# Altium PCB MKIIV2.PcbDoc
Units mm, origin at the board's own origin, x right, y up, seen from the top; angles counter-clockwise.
Board outline 51.16 x 28.42 mm, 2 copper layers (Top Layer, Bottom Layer); 24 components, 0 nets, 95 pads, 0 vias.
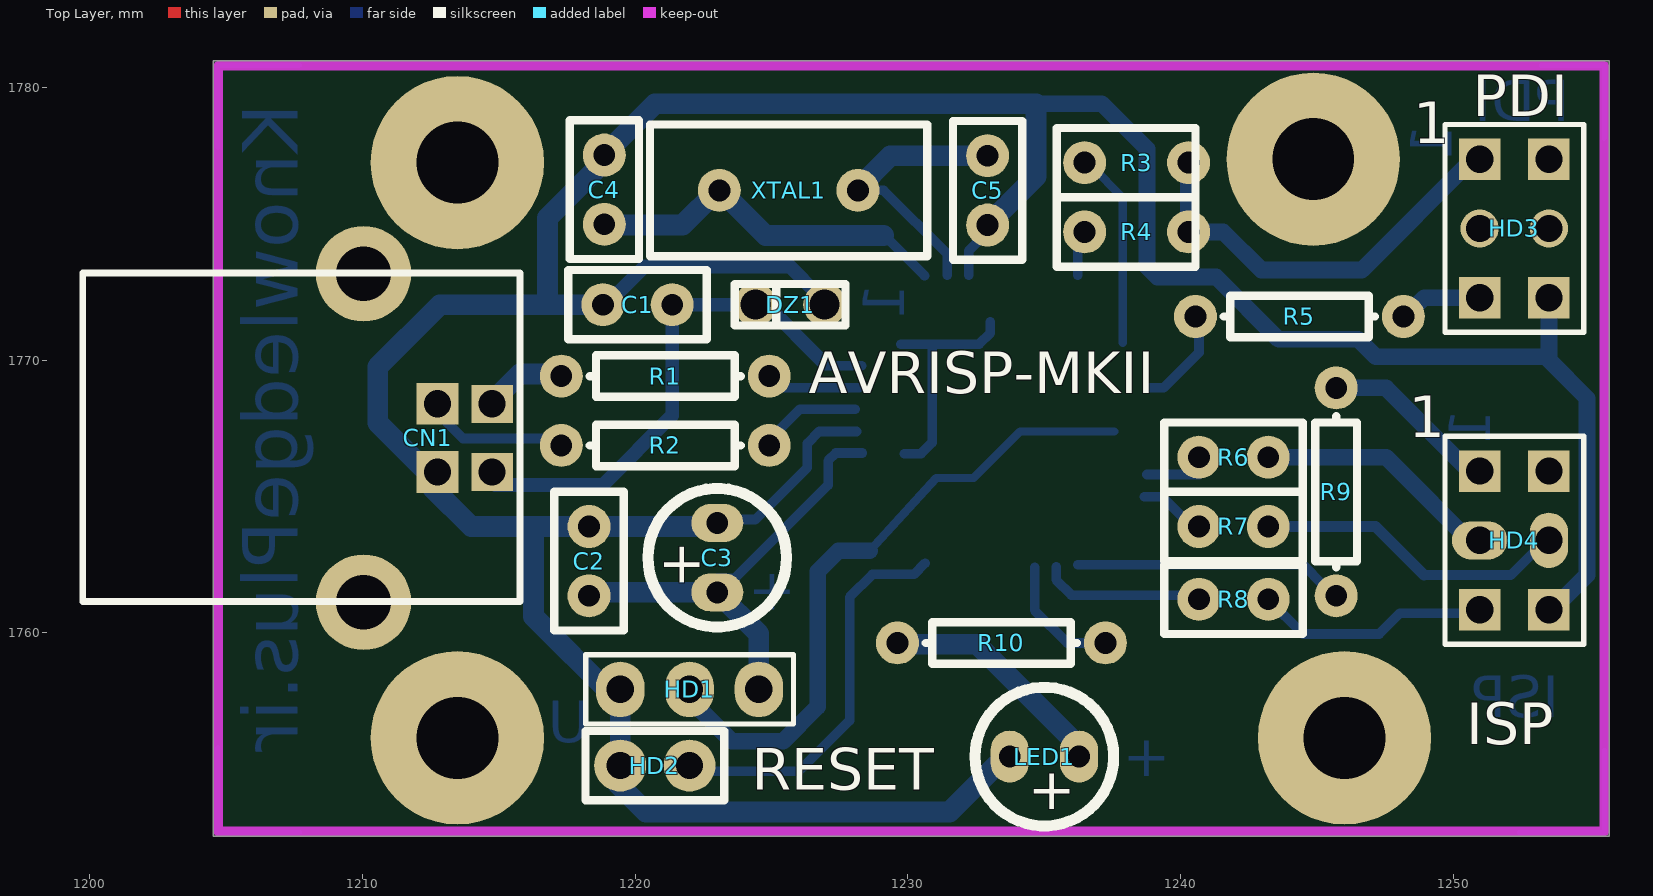
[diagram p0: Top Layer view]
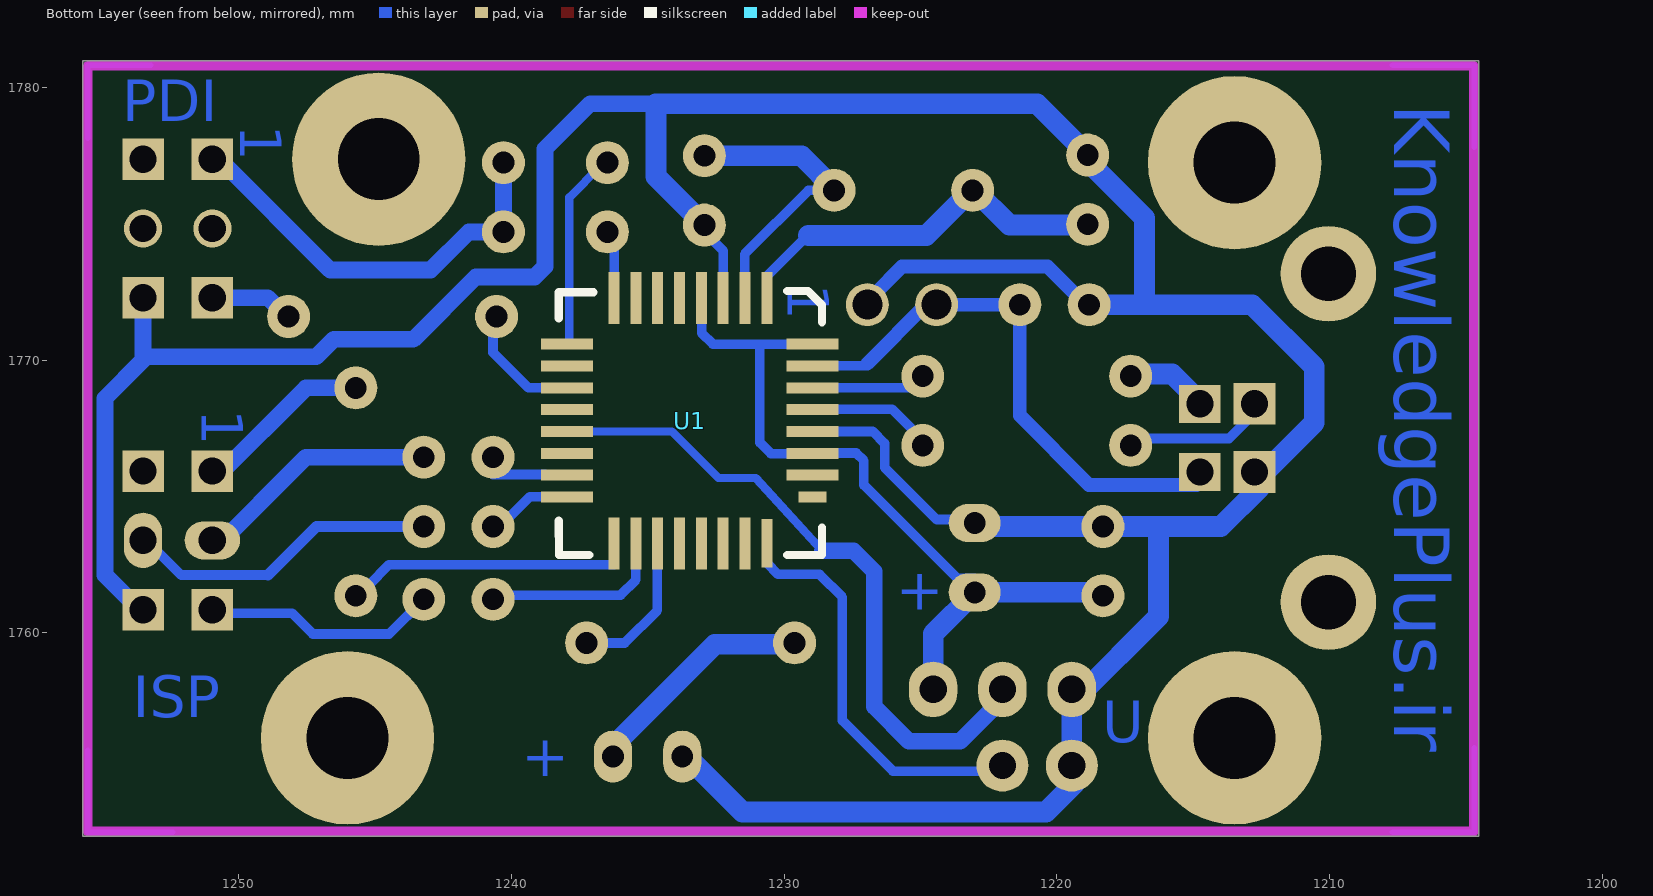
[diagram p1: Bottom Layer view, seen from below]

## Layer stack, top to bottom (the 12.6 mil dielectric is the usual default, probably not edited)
Top Layer: signal copper 0.0356
Dielectric: dielectric 0.32, FR-4, Dk 4.8
Bottom Layer: signal copper 0.0356

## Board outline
1204.544,1752.549 1255.7,1752.549 1255.7,1780.972 1204.544,1780.972

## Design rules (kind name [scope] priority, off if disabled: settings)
Clearance [All] p1: gap=0.254
PlaneClearance PlaneClearance_20 [HasPad('HD2-1')] p1: clearance=0.254
PlaneClearance PlaneClearance_19 [HasPad('HD2-2')] p2: clearance=0.254
PlaneClearance PlaneClearance_18 [HasPad('R10-1')] p3: clearance=0.254
PlaneClearance PlaneClearance_17 [HasPad('R10-2')] p4: clearance=0.254
PlaneClearance PlaneClearance_16 [HasPad('LED1-0')] p5: clearance=0.254
PlaneClearance PlaneClearance_15 [HasPad('CN1-0')] p6: clearance=0.254
PlaneClearance PlaneClearance_14 [HasPad('R1-1')] p7: clearance=0.254
PlaneClearance PlaneClearance_13 [HasPad('R1-2')] p8: clearance=0.254
PlaneClearance PlaneClearance_12 [HasPad('DZ1-0')] p9: clearance=0.254
PlaneClearance PlaneClearance_11 [HasPad('C3-0')] p10: clearance=0.254
PlaneClearance PlaneClearance_10 [HasPad('R2-2')] p11: clearance=0.254
PlaneClearance PlaneClearance_9 [HasPad('R2-1')] p12: clearance=0.254
PlaneClearance PlaneClearance_8 [HasPad('R5-2')] p13: clearance=0.254
PlaneClearance PlaneClearance_7 [HasPad('R5-1')] p14: clearance=0.254
PlaneClearance PlaneClearance_6 [HasPad('R9-1')] p15: clearance=0.254
PlaneClearance PlaneClearance_5 [HasPad('R9-2')] p16: clearance=0.254
PlaneClearance PlaneClearance_4 [HasPad('Free-1')] p17: clearance=0.254
PlaneClearance PlaneClearance_3 [HasPad('Free-2')] p18: clearance=0.254
PlaneClearance PlaneClearance_2 [HasPad('Free-3')] p19: clearance=0.254
PlaneClearance PlaneClearance_1 [HasPad('Free-4')] p20: clearance=0.254
PlaneClearance [All] p21: clearance=0.508
PolygonConnect [All] p1: connectstyle=Relief reliefconductorwidth=0.254 reliefentries=4 polygonreliefangle="90 Angle" airgapwidth=0.254
RoutingVias [All] p1: holewidth=0.711 width=1.27 viastyle="Through Hole" minholewidth=0.711 minwidth=1.27 maxholewidth=0.711 maxwidth=1.27
SolderMaskExpansion SolderMaskExpansion_24 [HasPad('HD1-1')] p1: expansion=0.102
SolderMaskExpansion SolderMaskExpansion_23 [HasPad('HD1-2')] p2: expansion=0.102
SolderMaskExpansion SolderMaskExpansion_22 [HasPad('HD1-3')] p3: expansion=0.102
SolderMaskExpansion SolderMaskExpansion_21 [HasPad('C1-0')] p4: expansion=0.102
SolderMaskExpansion SolderMaskExpansion_20 [HasPad('C2-0')] p5: expansion=0.102
SolderMaskExpansion SolderMaskExpansion_19 [HasPad('XTAL1-0')] p6: expansion=0.102
SolderMaskExpansion SolderMaskExpansion_18 [HasPad('C4-0')] p7: expansion=0.102
SolderMaskExpansion SolderMaskExpansion_17 [HasPad('C5-0')] p8: expansion=0.102
SolderMaskExpansion SolderMaskExpansion_16 [HasPad('R3-0')] p9: expansion=0.102
SolderMaskExpansion SolderMaskExpansion_15 [HasPad('R4-0')] p10: expansion=0.102
SolderMaskExpansion SolderMaskExpansion_14 [HasPad('R6-0')] p11: expansion=0.102
SolderMaskExpansion SolderMaskExpansion_13 [HasPad('R7-0')] p12: expansion=0.102
SolderMaskExpansion SolderMaskExpansion_12 [HasPad('R8-0')] p13: expansion=0.102
SolderMaskExpansion SolderMaskExpansion_11 [HasPad('HD3-VCC')] p14: expansion=0.102
SolderMaskExpansion SolderMaskExpansion_10 [HasPad('HD3-RST')] p15: expansion=0.102
SolderMaskExpansion SolderMaskExpansion_9 [HasPad('HD3-GND')] p16: expansion=0.102
SolderMaskExpansion SolderMaskExpansion_8 [HasPad('HD3-')] p17: expansion=0.102
SolderMaskExpansion SolderMaskExpansion_7 [HasPad('HD3-PDI')] p18: expansion=0.102
SolderMaskExpansion SolderMaskExpansion_6 [HasPad('HD4-MISO')] p19: expansion=0.102
SolderMaskExpansion SolderMaskExpansion_5 [HasPad('HD4-MOSI')] p20: expansion=0.102
SolderMaskExpansion SolderMaskExpansion_4 [HasPad('HD4-SCK')] p21: expansion=0.102
SolderMaskExpansion SolderMaskExpansion_3 [HasPad('HD4-GND')] p22: expansion=0.102
SolderMaskExpansion SolderMaskExpansion_2 [HasPad('HD4-RST')] p23: expansion=0.102
SolderMaskExpansion SolderMaskExpansion_1 [HasPad('HD4-VCC')] p24: expansion=0.102
SolderMaskExpansion [All] p25: expansion=0.051
Width [All] p1: maxlimit=0.254 minlimit=0.254 preferedwidth=0.254
27 further rules are at their usual default settings.

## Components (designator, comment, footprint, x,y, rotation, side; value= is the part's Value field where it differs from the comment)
C1 "100nF" RAD0.1#1 1218.819,1772.031 r0 top
C2 "100nF" RAD0.1#1 1218.311,1761.363 r90 top
C3 "1uF" RB.1/.2 1223.01,1761.49 r90 top
C4 "18pF" RAD0.1#1 1218.87,1777.517 r270 top
C5 "18pF" RAD0.1#1 1232.916,1774.952 r90 top
CN1 "USB B connector" USB_B 1210.056,1773.174 r270 top
DZ1 "1N4734" DIODE0.1 1224.407,1772.031 r270 top
HD1 "1x3 Pin header+jumper" VR5 1221.994,1757.934 r0 top
HD2 "1x2 Pin header+jumper" RAD0.1#2 1219.454,1755.14 r0 top
HD3 "2x3 Pin header" HDR2X3#1 1250.95,1777.365 r270 top
HD4 "2x3 Pin header" HDR2X3#2 1250.95,1765.935 r270 top
LED1 "LED" RB.1/.2 1236.269,1755.47 r180 top
R1 "22 ohm" AXIAL0.3 1224.915,1769.364 r180 top
R2 "22 ohm" AXIAL0.3 1224.915,1766.824 r180 top
R3 "220 ohm" RAD0.1#3 1236.726,1777.238 r0 top
R4 "220 ohm" RAD0.1#3 1236.726,1774.698 r0 top
R5 "33 ohm" AXIAL0.3 1240.536,1771.65 r0 top
R6 "33 ohm" RAD0.1#1 1240.663,1766.443 r0 top
R7 "33 ohm" RAD0.1#1 1240.663,1763.903 r0 top
R8 "33 ohm" RAD0.1#1 1240.663,1761.236 r0 top
R9 "33 ohm" AXIAL0.3 1245.743,1768.983 r270 top
R10 "470 ohm" AXIAL0.3 1237.234,1759.585 r180 top
U1 "AT90usb162" QFP32 1230.63,1772.285 r270 top
XTAL1 "8MHz" XTAL1 1228.166,1776.222 r180 top

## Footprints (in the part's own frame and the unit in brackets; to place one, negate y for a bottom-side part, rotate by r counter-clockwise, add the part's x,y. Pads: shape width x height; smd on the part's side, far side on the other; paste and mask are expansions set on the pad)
AXIAL0.3 [mil]
  round 62 hole 31.5: 1(0,-2) 2(300,-2)
  silkscreen extent 41,-32 259,28
DIODE0.1 [mil]
  round 62 hole 43.31: 0(0,100) 0(0,0)
  silkscreen extent -30,-30 30,130
HDR2X3#1 [mil]
  rect 60x60 hole 39.37: GND(200,100) PDI(0,0) RST(200,0) VCC(0,100)
  round 55 hole 39.37: ""(100,100) ""(100,0)
  silkscreen extent -50,-50 250,150
HDR2X3#2 [mil]
  rect 60x60 hole 39.37: GND(200,100) MISO(0,0) RST(200,0) VCC(0,100)
  oval 80x55 hole 39.37: MOSI(100,100)
  oval 55x80 hole 39.37: SCK(100,0)
  silkscreen extent -50,-50 250,150
QFP32 [mm]
  rect 1.905x0.406 smd far side: 1(0,0) 2(0,0.8) 3(0,1.6) 4(0,2.4) 5(0,3.2) 6(0,4) 7(0,4.8) 8(0,5.6) 17(9,5.6) 18(9,4.8) 19(9,4) 20(9,3.2) 21(9,2.4) 22(9,1.6) 23(9,0.8)
  rect 0.406x1.905 smd far side: 9(1.7,7.325) 10(2.5,7.325) 11(3.3,7.325) 12(4.1,7.325) 13(4.9,7.325) 14(5.7,7.325) 15(6.5,7.325) 16(7.3,7.325) 26(6.5,-1.675) 27(5.7,-1.675) 28(4.9,-1.675) 29(4.1,-1.675) 30(3.3,-1.675) 31(2.5,-1.675) 32(1.7,-1.675)
  rect 1.778x0.406 smd far side: 24(9,0)
  rect 0.406x1.016 smd far side: 25(7.3,-1.675)
RAD0.1#1 [mil]
  round 62 hole 31.5: 0(0,0) 0(100,0)
  silkscreen extent -50,-50 150,50
RAD0.1#2 [mil]
  round 75 hole 39.37: 1(0,0) 2(100,0)
  silkscreen extent -50,-50 150,50
RAD0.1#3 [mil]
  round 62 hole 31.5: 0(-10,0) 0(140,0)
  silkscreen extent -50,-50 150,50
RB.1/.2 [mm]
  oval 1.397x1.905 hole 0.8: 0(0,0) 0(2.54,0)
  silkscreen extent -1.27,-2.54 3.81,2.54
USB_B [mm]
  round 3.5 hole 2: 0(0.005,-0.01) 0(12.045,-0.01)
  rect 1.524x1.524 hole 1: 0(4.775,2.7) 0(7.275,2.7)
  rect 1.397x1.524 hole 1: 0(4.775,4.7) 0(7.275,4.7)
  silkscreen extent -0.03,-10.3 12.03,5.72
VR5 [mil]
  oval 70x80 hole 39.37: 1(-100,0) 2(0,0) 3(100,0)
  silkscreen extent -150,-50 150,50
XTAL1 [mil]
  round 62 hole 31.5: 0(0,0) 0(200,0)
  silkscreen extent -100,-95 300,95

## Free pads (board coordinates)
  round 6.35 hole 3: 1(1244.854,1777.365) 2(1245.997,1756.156) 3(1213.485,1756.156) 4(1213.485,1777.238)

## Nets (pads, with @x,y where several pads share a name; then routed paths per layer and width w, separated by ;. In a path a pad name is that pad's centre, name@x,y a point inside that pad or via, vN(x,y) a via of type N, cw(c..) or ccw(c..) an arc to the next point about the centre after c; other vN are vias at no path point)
pads on no net: C1.0 C2.0 C3.0 C4.0 C5.0 CN1.0 DZ1.0 HD1.1 HD1.2 HD1.3 HD2.1 HD2.2 HD3. HD3.GND HD3.PDI HD3.RST HD3.VCC HD4.GND HD4.MISO HD4.MOSI HD4.RST HD4.SCK HD4.VCC LED1.0 R1.1 R1.2 R2.1 R2.2 R3.0 R4.0 R5.1 R5.2 R6.0 R7.0 R8.0 R9.1 R9.2 R10.1 R10.2 U1.1 U1.2 U1.3 U1.4 U1.5 U1.6 U1.7 U1.8 U1.9 U1.10 U1.11 U1.12 U1.13 U1.14 U1.15 U1.16 U1.17 U1.18 U1.19 U1.20 U1.21 U1.22 U1.23 U1.24 U1.25 U1.26 U1.27 U1.28 U1.29 U1.30 U1.31 U1.32 XTAL1.0
copper on no net: | length 374.4
  Bottom Layer w0.203: 1204.7,1755.8 1204.7,1752.7 1207.7,1752.7 ; 1204.7,1777.8 1204.7,1780.8 1207.7,1780.8 ; 1252.4,1752.7 1255.522,1752.7 1255.522,1755.7 ; 1253.2,1780.8 1255.522,1780.8 1255.522,1778.127
  Bottom Layer w0.305: 1228.598,1763.014 1231.036,1765.681 1232.408,1765.681 1234.11,1767.383 1237.564,1767.383 ; 1236.726,1777.111 1237.869,1775.968 1237.869,1770.634
  Bottom Layer w0.356: 1212.723,1768.094 1213.688,1767.129 1216.863,1767.129 ; 1222.273,1754.937 1226.007,1754.937 1227.861,1756.791 1227.861,1761.312 1228.7,1762.15 1230.224,1762.15 1230.63,1762.557 ; 1222.883,1764.157 1224.407,1764.157 1226.312,1766.062 1226.312,1766.951 1226.744,1767.383 1228.115,1767.383 ; 1223.01,1761.998 1223.645,1761.998 1227.074,1765.427 1227.074,1766.316 1227.353,1766.595 1228.319,1766.595 ; 1224.661,1766.824 1226.033,1768.196 1228.065,1768.196 ; 1224.915,1768.983 1228.217,1768.983 ; 1227.023,1769.796 1228.293,1769.796 ; 1228.293,1776.222 1229.106,1776.222 1231.443,1773.885 1231.443,1773.123 ; 1229.131,1774.571 1230.605,1773.098 ; 1229.741,1770.583 1232.611,1770.583 1233.018,1770.99 1233.018,1771.396 ; 1229.868,1766.57 1230.478,1766.57 1230.884,1766.976 1230.884,1770.532 ; 1232.23,1773.123 1232.23,1774.012 1232.916,1774.698 ; 1234.643,1762.404 1234.643,1760.83 1235.837,1759.636 1237.132,1759.636 ; 1235.431,1762.43 1235.431,1761.947 1235.989,1761.388 1240.231,1761.388 ; 1236.218,1762.506 1244.473,1762.506 1245.235,1761.744 1245.489,1761.744 ; 1236.218,1773.123 1236.218,1774.444 ; 1238.656,1764.995 1239.317,1764.995 1240.409,1763.903 1240.282,1763.903 ; 1238.758,1765.808 1240.663,1765.808 ; 1238.809,1768.983 1239.368,1768.983 1240.663,1770.278 1240.663,1771.421 ; 1243.203,1761.236 1244.473,1759.966 1247.267,1759.966 1248.029,1760.728 1250.442,1760.728 ; 1248.918,1762.125 1252.093,1762.125 1252.982,1763.014
  Bottom Layer w0.406: 1243.33,1763.903 1247.14,1763.903 1248.918,1762.125
  Bottom Layer w0.508: 1214.882,1765.427 1218.819,1765.427 1221.359,1767.967 1221.359,1772.031 1224.788,1772.031 1226.947,1769.872 ; 1218.946,1772.031 1220.343,1773.428 1225.677,1773.428 1226.693,1772.412
  Bottom Layer w0.61: 1222.299,1757.274 1223.543,1756.029 1225.423,1756.029 1226.693,1757.299 1226.693,1762.252 1227.455,1763.014 1228.598,1763.014 ; 1234.694,1779.397 1237.107,1779.397 1238.758,1777.746 1238.758,1773.428 1239.139,1773.047 1241.298,1773.047 1243.584,1770.761 1246.505,1770.761 1247.14,1770.126 1253.49,1770.126 ; 1240.282,1777.238 1240.282,1774.698 1241.552,1774.698 1242.949,1773.301 1246.632,1773.301 1250.696,1777.365 ; 1243.203,1766.443 1247.521,1766.443 1250.95,1763.014 ; 1245.743,1768.983 1247.521,1768.983 1250.696,1765.808 ; 1248.156,1771.523 1248.918,1772.285 1250.95,1772.285 ; 1253.49,1772.158 1253.49,1769.999 1254.887,1768.602 1254.887,1762.125 1253.744,1760.982
  Bottom Layer w0.762: 1212.469,1765.808 1210.564,1767.713 1210.564,1769.745 1212.85,1772.031 1218.819,1772.031 ; 1212.596,1765.3 1213.993,1763.903 1223.137,1763.903 ; 1214.755,1768.475 1215.771,1769.491 1217.422,1769.491 ; 1216.279,1763.903 1216.279,1760.601 1219.2,1757.68 ; 1216.787,1772.158 1216.787,1775.206 1218.692,1777.111 ; 1218.311,1761.49 1223.01,1761.49 1224.534,1759.966 1224.534,1757.426 ; 1218.819,1774.952 1221.74,1774.952 1223.01,1776.222 ; 1218.946,1777.619 1220.724,1779.397 1234.694,1779.397 1234.694,1776.73 1232.916,1774.952 ; 1219.352,1754.48 1220.394,1753.438 1231.519,1753.438 1233.551,1755.47 ; 1219.454,1755.064 1219.454,1757.934 ; 1223.137,1776.222 1224.788,1774.571 1229.106,1774.571 ; 1228.09,1776.222 1229.36,1777.492 1232.916,1777.492 ; 1229.614,1759.585 1232.535,1759.585 1236.345,1755.775

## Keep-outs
Keep-Out Layer:
  lines w0.356: 1204.722,1752.727 1204.722,1780.794 1255.522,1780.794 1255.522,1752.727 1204.722,1752.727

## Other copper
Bottom Layer:
  text "KnowledgePlus.ir" at 1207.643,1779.397 h2.03 r90
  text "PDI" at 1254.252,1778.762 h1.52
  text "1" at 1249.934,1778.635 h1.52 r90
  text "1" at 1229.868,1772.793 h1.52 r90
  text "1" at 1251.331,1768.196 h1.52 r90
  text "+" at 1224.153,1760.855 h1.52
  text "ISP" at 1253.871,1756.918 h1.52
  text "U" at 1218.336,1756.004 h1.52
  text "+" at 1237.869,1754.759 h1.52

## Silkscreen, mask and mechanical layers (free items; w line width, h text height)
Top Overlay:
  text "PDI" at 1250.696,1778.94 h1.52
  text "1" at 1248.512,1777.949 h1.52
  text "AVRISP-MKII" at 1226.363,1768.78 h1.52
  text "1" at 1248.359,1767.18 h1.52
  text "ISP" at 1250.467,1755.927 h1.52
  text "RESET" at 1224.28,1754.251 h1.52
